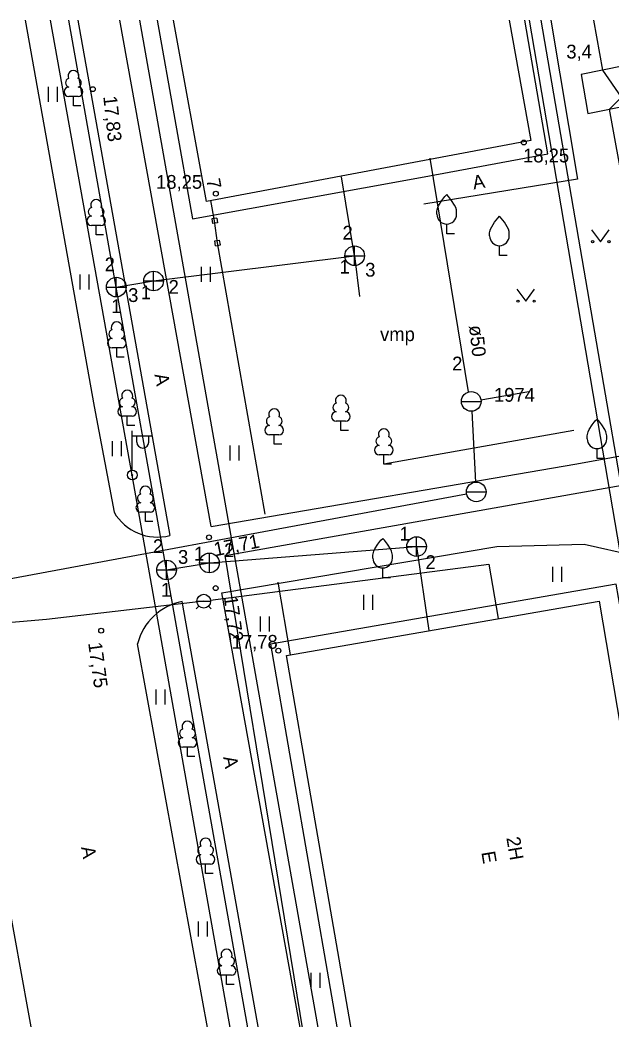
# Model space of a CAD drawing. Extents: x 713540 to 713867, y 6589774 to 6590061.
# Drawn here: x 713670.7 to 713700.8, y 6590009.8 to 6590060.6 of the extents above; entities that cross this region are included whole.
import ezdxf

# ---------------------------------------------------------------- set-up
doc = ezdxf.new("R2010")
doc.units = 0
for name, color, linetype in [('AED', 7, 'Continuous'), ('HALJASTUS', 7, 'Continuous'), ('HOONE', 7, 'Continuous'), ('HOONEDET', 7, 'Continuous'), ('KAEVU_NR', 7, 'Continuous'), ('KKAEV', 7, 'Continuous'), ('KORGUS', 7, 'Continuous'), ('KTRASS', 7, 'Continuous'), ('MPKAABEL', 7, 'Continuous'), ('POST', 7, 'Continuous'), ('PUU', 7, 'Continuous'), ('SITRASS', 7, 'Continuous'), ('TEE', 7, 'Continuous'), ('TORU NR', 7, 'Continuous'), ('TTRASS', 7, 'Continuous'), ('VKAEV', 7, 'Continuous'), ('VTRASS', 7, 'Continuous'), ('Слой 1', 7, 'Continuous')]:
    doc.layers.add(name, color=color, linetype=linetype)

msp = doc.modelspace()

# ---------------------------------------------------------------- linework, layer by layer
at = {"layer": 'AED'}
for p, q in [((713680.725, 6590050.571), (713680.477, 6590050.535)), ((713680.725, 6590050.571), (713680.76, 6590050.324)), ((713680.477, 6590050.535), (713680.513, 6590050.288)), ((713680.76, 6590050.324), (713680.513, 6590050.288)), ((713680.624, 6590049.417), (713680.871, 6590049.455)), ((713680.662, 6590049.17), (713680.624, 6590049.417)), ((713680.662, 6590049.17), (713680.91, 6590049.208)), ((713680.91, 6590049.208), (713680.871, 6590049.455))]:
    msp.add_line(p, q, dxfattribs=at)
for points in [[(713680.619, 6590050.429), (713680.432, 6590051.459)], [(713683.186, 6590035.532), (713680.767, 6590049.312)], [(713683.825, 6590032.076), (713684.466, 6590028.387)]]:
    msp.add_lwpolyline(points, dxfattribs=at)
at = {"layer": 'HALJASTUS'}
for p, q in [((713672.15, 6590057.234), (713672.15, 6590056.472)), ((713672.606, 6590057.234), (713672.606, 6590056.472)), ((713699.777, 6590049.977), (713700.24, 6590049.37)), ((713700.24, 6590049.37), (713700.686, 6590049.977)), ((713679.941, 6590048.098), (713679.941, 6590047.337)), ((713680.397, 6590048.098), (713680.397, 6590047.337)), ((713673.772, 6590047.706), (713673.772, 6590046.944)), ((713674.227, 6590047.706), (713674.227, 6590046.944)), ((713695.977, 6590046.957), (713696.44, 6590046.35)), ((713696.44, 6590046.35), (713696.886, 6590046.957)), ((713675.415, 6590039.242), (713675.415, 6590038.481)), ((713675.87, 6590039.242), (713675.87, 6590038.481)), ((713681.386, 6590039.019), (713681.386, 6590038.258)), ((713681.841, 6590039.019), (713681.841, 6590038.258)), ((713697.801, 6590032.855), (713697.801, 6590032.094)), ((713698.256, 6590032.855), (713698.256, 6590032.094)), ((713688.185, 6590031.427), (713688.185, 6590030.666)), ((713688.64, 6590031.427), (713688.64, 6590030.666)), ((713682.928, 6590030.322), (713682.928, 6590029.561)), ((713683.383, 6590030.322), (713683.383, 6590029.561)), ((713677.627, 6590026.626), (713677.627, 6590025.865)), ((713678.082, 6590026.626), (713678.082, 6590025.865)), ((713679.775, 6590014.826), (713679.775, 6590014.065)), ((713680.23, 6590014.826), (713680.23, 6590014.065)), ((713685.512, 6590012.227), (713685.512, 6590011.466)), ((713685.967, 6590012.227), (713685.967, 6590011.466))]:
    msp.add_line(p, q, dxfattribs=at)
for points in [[(713680.767, 6590049.312), (713680.619, 6590050.429)], [(713698.882, 6590039.786), (713689.223, 6590038.067)]]:
    msp.add_lwpolyline(points, dxfattribs=at)
for centre in [(713699.839, 6590049.37), (713700.668, 6590049.37), (713696.039, 6590046.35), (713696.868, 6590046.35)]:
    msp.add_circle(centre, 0.055, dxfattribs=at)
at = {"layer": 'HOONE'}
for points in [[(713696.688, 6590054.508), (713680.198, 6590051.417), (713678.525, 6590060.636)], [(713695.591, 6590060.636), (713696.688, 6590054.508)], [(713703.989, 6590008.604), (713688.188, 6590005.782), (713684.27, 6590028.353), (713700.164, 6590031.112), (713703.989, 6590008.604)]]:
    msp.add_lwpolyline(points, dxfattribs=at)
at = {"layer": 'HOONEDET'}
for points in [[(713677.688, 6590060.636), (713679.494, 6590050.533), (713691.09, 6590052.637), (713697.552, 6590053.831), (713696.396, 6590060.636)], [(713702.7, 6590022.49), (713701.04, 6590031.975), (713683.46, 6590028.923), (713687.599, 6590005.08), (713705.008, 6590008.102), (713703.29, 6590019.02)]]:
    msp.add_lwpolyline(points, dxfattribs=at)
at = {"layer": 'KKAEV'}
for p, q in [((713687.738, 6590048.158), (713687.738, 6590049.158)), ((713687.238, 6590048.658), (713688.238, 6590048.658)), ((713675.618, 6590046.564), (713675.618, 6590047.564)), ((713677.515, 6590046.876), (713677.515, 6590047.876)), ((713675.118, 6590047.064), (713676.118, 6590047.064)), ((713677.015, 6590047.376), (713678.015, 6590047.376)), ((713690.883, 6590033.381), (713690.883, 6590034.381)), ((713690.383, 6590033.881), (713691.383, 6590033.881)), ((713680.353, 6590032.55), (713680.353, 6590033.55)), ((713678.174, 6590032.191), (713678.174, 6590033.191)), ((713679.853, 6590033.05), (713680.853, 6590033.05)), ((713677.674, 6590032.691), (713678.674, 6590032.691))]:
    msp.add_line(p, q, dxfattribs=at)
for centre in [(713687.738, 6590048.658), (713675.618, 6590047.064), (713677.515, 6590047.376), (713690.883, 6590033.881), (713680.353, 6590033.05), (713678.174, 6590032.691)]:
    msp.add_circle(centre, 0.5, dxfattribs=at)
at = {"layer": 'KORGUS'}
for centre in [(713674.42, 6590057.12), (713696.34, 6590054.41), (713680.68, 6590051.81), (713680.33, 6590034.35), (713680.67, 6590031.77), (713674.85, 6590029.61), (713683.86, 6590028.59)]:
    msp.add_circle(centre, 0.125, dxfattribs=at)
at = {"layer": 'KTRASS'}
for p, q in [((713675.618, 6590047.064), (713673.199, 6590060.636)), ((713687.738, 6590048.658), (713687.077, 6590052.665)), ((713677.515, 6590047.376), (713687.738, 6590048.658)), ((713687.738, 6590048.658), (713687.98, 6590046.589)), ((713675.618, 6590047.064), (713677.515, 6590047.376)), ((713678.174, 6590032.691), (713675.618, 6590047.064)), ((713680.353, 6590033.05), (713690.883, 6590033.881)), ((713690.883, 6590033.881), (713691.512, 6590029.61)), ((713678.174, 6590032.691), (713680.353, 6590033.05)), ((713683.799, 6590000.987), (713678.174, 6590032.691))]:
    msp.add_line(p, q, dxfattribs=at)
at = {"layer": 'MPKAABEL'}
for points in [[(713692.718, 6589944.775), (713692.321, 6589946.558), (713690.066, 6589959.298), (713688.999, 6589967.843), (713683.646, 6589996.839), (713676.43, 6590037.515), (713672.265, 6590060.636)], [(713704.5, 6590018.38), (713697.217, 6590060.636)]]:
    msp.add_lwpolyline(points, dxfattribs=at)
at = {"layer": 'POST'}
for p, q in [((713676.43, 6590037.765), (713676.43, 6590039.765)), ((713676.43, 6590039.515), (713677.43, 6590039.515)), ((713676.656, 6590039.194), (713676.656, 6590039.515)), ((713677.269, 6590039.194), (713677.269, 6590039.515))]:
    msp.add_line(p, q, dxfattribs=at)
for radius in [0.25, 0.0234]:
    msp.add_circle((713676.43, 6590037.515), radius, dxfattribs=at)
msp.add_arc((713676.963, 6590039.194), 0.306, 180, 0, dxfattribs=at)
at = {"layer": 'PUU'}
for p, q in [((713673.677, 6590056.75), (713673.197, 6590056.75)), ((713673.437, 6590056.275), (713673.437, 6590056.75)), ((713673.817, 6590056.275), (713673.437, 6590056.275)), ((713674.835, 6590050.193), (713674.355, 6590050.193)), ((713674.595, 6590049.718), (713674.595, 6590050.193)), ((713692.42, 6590049.77), (713692.42, 6590050.27)), ((713674.975, 6590049.718), (713674.595, 6590049.718)), ((713692.82, 6590049.77), (713692.42, 6590049.77)), ((713695.1, 6590048.67), (713695.1, 6590049.17)), ((713695.5, 6590048.67), (713695.1, 6590048.67)), ((713675.88, 6590043.974), (713675.4, 6590043.974)), ((713675.64, 6590043.499), (713675.64, 6590043.974)), ((713676.02, 6590043.499), (713675.64, 6590043.499)), ((713676.417, 6590040.504), (713675.937, 6590040.504)), ((713676.177, 6590040.029), (713676.177, 6590040.504)), ((713676.557, 6590040.029), (713676.177, 6590040.029)), ((713687.277, 6590040.248), (713686.797, 6590040.248)), ((713687.037, 6590039.773), (713687.037, 6590040.248)), ((713683.89, 6590039.555), (713683.41, 6590039.555)), ((713683.65, 6590039.08), (713683.65, 6590039.555)), ((713687.417, 6590039.773), (713687.037, 6590039.773)), ((713684.03, 6590039.08), (713683.65, 6590039.08)), ((713689.463, 6590038.542), (713688.983, 6590038.542)), ((713689.223, 6590038.067), (713689.223, 6590038.542)), ((713700.06, 6590038.36), (713700.06, 6590038.86)), ((713689.603, 6590038.067), (713689.223, 6590038.067)), ((713700.46, 6590038.36), (713700.06, 6590038.36)), ((713677.335, 6590035.624), (713676.855, 6590035.624)), ((713677.095, 6590035.149), (713677.095, 6590035.624)), ((713677.475, 6590035.149), (713677.095, 6590035.149)), ((713689.163, 6590032.298), (713689.163, 6590032.798)), ((713689.563, 6590032.298), (713689.163, 6590032.298)), ((713679.474, 6590023.687), (713678.994, 6590023.687)), ((713679.234, 6590023.212), (713679.234, 6590023.687)), ((713679.614, 6590023.212), (713679.234, 6590023.212)), ((713680.4, 6590017.749), (713679.92, 6590017.749)), ((713680.16, 6590017.274), (713680.16, 6590017.749)), ((713680.54, 6590017.274), (713680.16, 6590017.274)), ((713681.469, 6590012.098), (713680.989, 6590012.098)), ((713681.229, 6590011.623), (713681.229, 6590012.098)), ((713681.609, 6590011.623), (713681.229, 6590011.623))]:
    msp.add_line(p, q, dxfattribs=at)
for points in [[(713691.92, 6590050.77), (713691.92, 6590050.92), (713691.93, 6590050.985), (713691.965, 6590051.115), (713692.025, 6590051.235), (713692.17, 6590051.47), (713692.33, 6590051.675), (713692.42, 6590051.77)], [(713692.92, 6590050.77), (713692.92, 6590050.92), (713692.91, 6590050.985), (713692.875, 6590051.115), (713692.815, 6590051.235), (713692.67, 6590051.47), (713692.51, 6590051.675), (713692.42, 6590051.77)], [(713694.6, 6590049.67), (713694.6, 6590049.82), (713694.61, 6590049.885), (713694.645, 6590050.015), (713694.705, 6590050.135), (713694.85, 6590050.37), (713695.01, 6590050.575), (713695.1, 6590050.67)], [(713695.6, 6590049.67), (713695.6, 6590049.82), (713695.59, 6590049.885), (713695.555, 6590050.015), (713695.495, 6590050.135), (713695.35, 6590050.37), (713695.19, 6590050.575), (713695.1, 6590050.67)], [(713699.56, 6590039.36), (713699.56, 6590039.51), (713699.57, 6590039.575), (713699.605, 6590039.705), (713699.665, 6590039.825), (713699.81, 6590040.06), (713699.97, 6590040.265), (713700.06, 6590040.36)], [(713700.56, 6590039.36), (713700.56, 6590039.51), (713700.55, 6590039.575), (713700.515, 6590039.705), (713700.455, 6590039.825), (713700.31, 6590040.06), (713700.15, 6590040.265), (713700.06, 6590040.36)], [(713688.663, 6590033.298), (713688.663, 6590033.448), (713688.673, 6590033.513), (713688.708, 6590033.643), (713688.768, 6590033.763), (713688.913, 6590033.998), (713689.073, 6590034.203), (713689.163, 6590034.298)], [(713689.663, 6590033.298), (713689.663, 6590033.448), (713689.653, 6590033.513), (713689.618, 6590033.643), (713689.558, 6590033.763), (713689.413, 6590033.998), (713689.253, 6590034.203), (713689.163, 6590034.298)]]:
    msp.add_lwpolyline(points, dxfattribs=at)
for centre, radius, start, end in [((713673.437, 6590057.795), 0.277, 332.5799, 207.4201), ((713673.2, 6590056.987), 0.238, 90.0016, 269.3953), ((713673.267, 6590057.448), 0.233, 109.0217, 253.1415), ((713673.607, 6590057.448), 0.233, 286.8508, 70.9859), ((713673.675, 6590056.987), 0.238, 270.6047, 89.9984), ((713674.425, 6590050.891), 0.233, 109.0217, 253.1415), ((713674.595, 6590051.238), 0.277, 332.5799, 207.4201), ((713674.765, 6590050.891), 0.233, 286.8508, 70.9859), ((713674.358, 6590050.431), 0.238, 90.0016, 269.3953), ((713674.833, 6590050.431), 0.238, 270.6047, 89.9984), ((713692.42, 6590050.77), 0.5, 180, 0), ((713695.1, 6590049.67), 0.5, 180, 0), ((713675.64, 6590045.019), 0.277, 332.5799, 207.4201), ((713675.47, 6590044.672), 0.233, 109.0217, 253.1415), ((713675.81, 6590044.672), 0.233, 286.8508, 70.9859), ((713675.403, 6590044.212), 0.238, 90.0016, 269.3953), ((713675.878, 6590044.212), 0.238, 270.6047, 89.9984), ((713676.007, 6590041.201), 0.233, 109.0217, 253.1415), ((713676.177, 6590041.549), 0.277, 332.5799, 207.4201), ((713676.347, 6590041.201), 0.233, 286.8508, 70.9859), ((713687.037, 6590041.293), 0.277, 332.5799, 207.4201), ((713675.939, 6590040.741), 0.238, 90.0016, 269.3953), ((713676.414, 6590040.741), 0.238, 270.6047, 89.9984), ((713686.867, 6590040.946), 0.233, 109.0217, 253.1415), ((713687.207, 6590040.946), 0.233, 286.8508, 70.9859), ((713683.48, 6590040.253), 0.233, 109.0217, 253.1415), ((713683.65, 6590040.6), 0.277, 332.5799, 207.4201), ((713683.82, 6590040.253), 0.233, 286.8508, 70.9859), ((713686.8, 6590040.486), 0.238, 90.0016, 269.3953), ((713687.275, 6590040.486), 0.238, 270.6047, 89.9984), ((713683.413, 6590039.792), 0.238, 90.0016, 269.3953), ((713683.887, 6590039.792), 0.238, 270.6047, 89.9984), ((713689.053, 6590039.24), 0.233, 109.0217, 253.1415), ((713689.223, 6590039.587), 0.277, 332.5799, 207.4201), ((713689.393, 6590039.24), 0.233, 286.8508, 70.9859), ((713688.986, 6590038.78), 0.238, 90.0016, 269.3953), ((713689.461, 6590038.78), 0.238, 270.6047, 89.9984), ((713700.06, 6590039.36), 0.5, 180, 0), ((713677.095, 6590036.669), 0.277, 332.5799, 207.4201), ((713676.925, 6590036.321), 0.233, 109.0217, 253.1415), ((713677.265, 6590036.321), 0.233, 286.8508, 70.9859), ((713676.857, 6590035.861), 0.238, 90.0016, 269.3953), ((713677.332, 6590035.861), 0.238, 270.6047, 89.9984), ((713689.163, 6590033.298), 0.5, 180, 0), ((713679.234, 6590024.732), 0.277, 332.5799, 207.4201), ((713678.997, 6590023.925), 0.238, 90.0016, 269.3953), ((713679.064, 6590024.385), 0.233, 109.0217, 253.1415), ((713679.404, 6590024.385), 0.233, 286.8508, 70.9859), ((713679.472, 6590023.925), 0.238, 270.6047, 89.9984), ((713680.16, 6590018.794), 0.277, 332.5799, 207.4201), ((713679.99, 6590018.447), 0.233, 109.0217, 253.1415), ((713680.331, 6590018.447), 0.233, 286.8508, 70.9859), ((713679.923, 6590017.987), 0.238, 90.0016, 269.3953), ((713680.398, 6590017.987), 0.238, 270.6047, 89.9984), ((713681.059, 6590012.796), 0.233, 109.0217, 253.1415), ((713681.229, 6590013.143), 0.277, 332.5799, 207.4201), ((713681.399, 6590012.796), 0.233, 286.8508, 70.9859), ((713680.992, 6590012.336), 0.238, 90.0016, 269.3953), ((713681.467, 6590012.336), 0.238, 270.6047, 89.9984)]:
    msp.add_arc(centre, radius, start, end, dxfattribs=at)
at = {"layer": 'SITRASS'}
for points in [[(713686.407, 6590006.478), (713676.816, 6590060.636)], [(713701.76, 6590021.73), (713703.22, 6590021.99), (713696.636, 6590060.636)]]:
    msp.add_lwpolyline(points, dxfattribs=at)
at = {"layer": 'TEE'}
for points in [[(713672.229, 6590004.328), (713665.804, 6590039.691), (713661.981, 6590060.636)], [(713670.99, 6590060.636), (713674.495, 6590040.993), (713675.505, 6590035.629)], [(713673.661, 6590060.636), (713678.338, 6590034.438)], [(713680.447, 6590034.893), (713675.793, 6590060.636)], [(713697.719, 6590060.636), (713699.06, 6590052.55), (713691.26, 6590051.285)], [(713680.447, 6590034.893), (713699.035, 6590038.091), (713712.76, 6590040.59)], [(713680.98, 6590031.537), (713694.963, 6590033.879)], [(713694.963, 6590033.879), (713699.404, 6590034.01), (713701.97, 6590033.42), (713702.95, 6590032.75), (713703.89, 6590031.91), (713705.78, 6590021.64), (713703.4, 6590021.18)], [(713692.595, 6589981.212), (713692.532, 6589981.556), (713695.416, 6589982.083), (713693.785, 6589991.005), (713688.468, 6589989.986), (713680.98, 6590031.537)], [(713691.7, 6589959.557), (713688.046, 6589980.323), (713678.974, 6590031.096)], [(713689.318, 6589959.578), (713688.035, 6589966.571), (713686.357, 6589979.631), (713686.045, 6589981.554), (713684.475, 6589986.323), (713676.697, 6590028.946)]]:
    msp.add_lwpolyline(points, dxfattribs=at)
for centre, radius, start, end in [((713677.715, 6590036.921), 2.56, 210.3089, 284.0789), ((713679.545, 6590028.212), 2.94, 101.1914, 165.5428)]:
    msp.add_arc(centre, radius, start, end, dxfattribs=at)
at = {"layer": 'TTRASS'}
for points in [[(713701.3, 6590056.71), (713700.36, 6590058.09), (713699.9, 6590060.636)], [(713699.25, 6590057.87), (713699.59, 6590055.89), (713701.78, 6590056.33), (713701.42, 6590058.31), (713699.25, 6590057.87)], [(713707.3, 6590021.94), (713706.8, 6590022.64), (713700.69, 6590056.11), (713701.3, 6590056.71)]]:
    msp.add_lwpolyline(points, dxfattribs=at)
at = {"layer": 'VKAEV'}
for p, q in [((713693.163, 6590041.253), (713694.163, 6590041.253)), ((713693.417, 6590036.66), (713694.417, 6590036.66)), ((713679.815, 6590030.858), (713679.675, 6590030.718)), ((713679.712, 6590031.105), (713680.412, 6590031.105)), ((713680.309, 6590030.858), (713680.449, 6590030.718))]:
    msp.add_line(p, q, dxfattribs=at)
for centre, radius in [((713693.663, 6590041.253), 0.5), ((713693.917, 6590036.66), 0.5), ((713680.062, 6590031.105), 0.35)]:
    msp.add_circle(centre, radius, dxfattribs=at)
at = {"layer": 'VTRASS'}
for points in [[(713693.526, 6590041.751), (713691.58, 6590053.62)], [(713694.156, 6590041.338), (713696.596, 6590041.76)], [(713693.691, 6590040.754), (713693.889, 6590037.16)], [(713665.322, 6590031.349), (713693.426, 6590036.568)], [(713680.409, 6590031.15), (713694.564, 6590032.995), (713695.035, 6590030.222)], [(713680.062, 6590031.105), (713672.07, 6590030.177), (713664.208, 6590029.493)]]:
    msp.add_lwpolyline(points, dxfattribs=at)
at = {"layer": 'Слой 1'}
msp.add_lwpolyline([(713713.11, 6590039.08), (713713.69, 6590035.37), (713718.88, 6589999.87), (713712.56, 6589991.28), (713713.13, 6589989.8), (713701.84, 6589988.96), (713702.78, 6589983.59), (713689.74, 6589981), (713681.15, 6590033.42)], close=True, dxfattribs=at)

# ---------------------------------------------------------------- texts
at = {"layer": 'HALJASTUS'}
msp.add_text('vmp', height=0.7, dxfattribs=at).set_placement((713689.03, 6590044.321))
at = {"layer": 'HOONE'}
for s, rotation, p in [('7', 280.6008, (713680.191, 6590052.52)), ('2H', 279.6065, (713695.448, 6590019.08)), ('E', 279.6065, (713694.178, 6590018.346))]:
    msp.add_text(s, height=0.7, rotation=rotation, dxfattribs=at).set_placement(p)
at = {"layer": 'KAEVU_NR'}
msp.add_text('1974', height=0.7, dxfattribs=at).set_placement((713694.822, 6590041.24))
at = {"layer": 'KORGUS'}
for s, rotation, p in [('17,83', 276.1702, (713674.953, 6590056.747)), ('17,71', 11.1006, (713680.648, 6590033.387)), ('17,72', 277.7119, (713681.081, 6590031.337)), ('17,75', 277.7119, (713674.186, 6590028.98))]:
    msp.add_text(s, height=0.7, rotation=rotation, dxfattribs=at).set_placement(p)
for s, p in [('18,25', (713696.301, 6590053.4)), ('18,25', (713677.641, 6590052.06)), ('17,78', (713681.482, 6590028.69))]:
    msp.add_text(s, height=0.7, dxfattribs=at).set_placement(p)
at = {"layer": 'TEE'}
for rotation, p in [(9.326, (713693.789, 6590052.022)), (280.8621, (713677.554, 6590042.617)), (280.5735, (713681.046, 6590023.179)), (279.9852, (713673.824, 6590018.6))]:
    msp.add_text('A', height=0.7, rotation=rotation, dxfattribs=at).set_placement(p)
at = {"layer": 'TORU NR'}
for s, p in [('3,4', (713698.499, 6590058.68)), ('2', (713687.12, 6590049.478)), ('2', (713675.029, 6590047.87)), ('1', (713686.968, 6590047.749)), ('3', (713688.273, 6590047.597)), ('3', (713676.22, 6590046.308)), ('1', (713676.865, 6590046.444)), ('2', (713678.276, 6590046.725)), ('1', (713675.356, 6590045.746)), ('2', (713692.694, 6590042.83)), ('1', (713690.017, 6590034.187)), ('2', (713677.479, 6590033.55)), ('1', (713679.565, 6590033.17)), ('2', (713681.097, 6590033.345)), ('3', (713678.754, 6590033.004)), ('2', (713691.337, 6590032.738)), ('1', (713677.889, 6590031.335))]:
    msp.add_text(s, height=0.7, dxfattribs=at).set_placement(p)
msp.add_text('ø50', height=0.7, rotation=276.1939, dxfattribs=at).set_placement((713693.554, 6590045.096))

doc.saveas('drawing.dxf')
